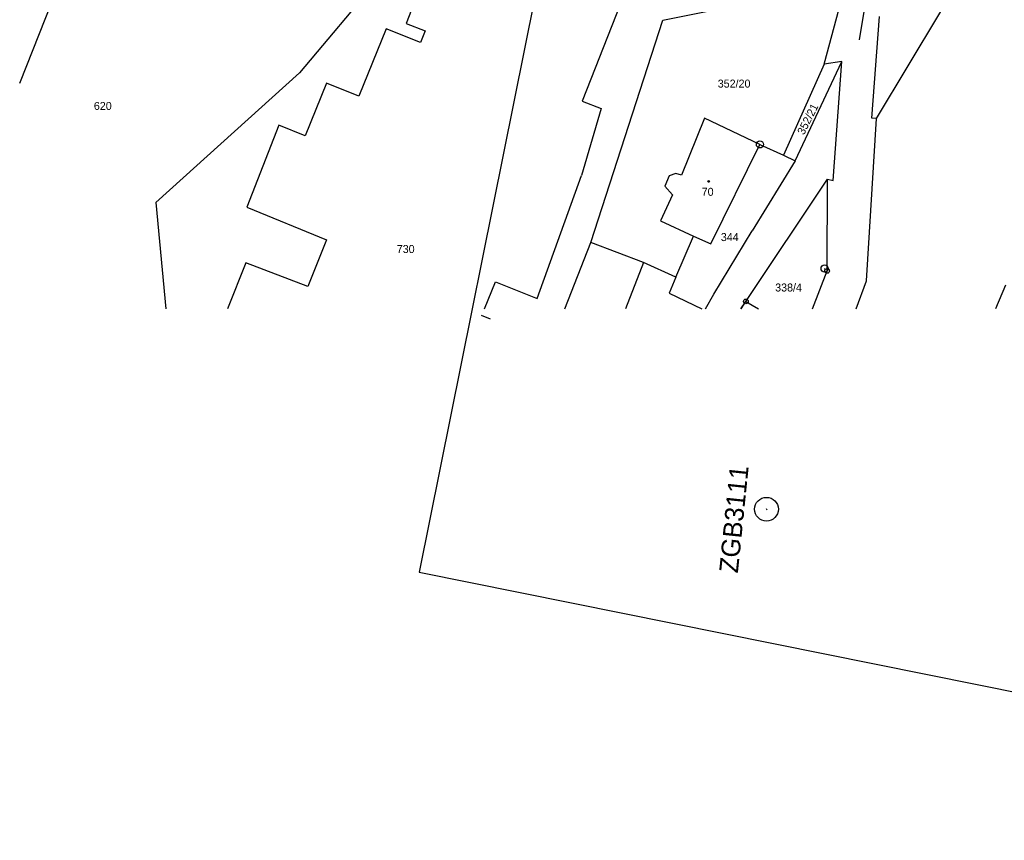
# Model space of a CAD drawing. Extents: x -778045 to -777594, y -1202682 to -1202213.
# Drawn here: x -778044.8 to -777835.6, y -1202682.1 to -1202507.7 of the extents above; entities that cross this region are included whole.
import ezdxf

# ---------------------------------------------------------------- set-up
doc = ezdxf.new("R2010")
doc.units = 0
for name, color, linetype in [('GD_Starý stav', 7, 'Continuous'), ('Katastr_HRANICE DRÁHY', 7, 'Continuous'), ('Katastr_Hranice parcel', 7, 'Continuous'), ('Katastr_Parcelní čísla', 7, 'Continuous'), ('Katastr_Slučkované čáry', 7, 'Continuous'), ('Katastr_Značky kultur', 7, 'Continuous'), ('ŽBP', 7, 'Continuous')]:
    doc.layers.add(name, color=color, linetype=linetype)

msp = doc.modelspace()

# ---------------------------------------------------------------- linework, layer by layer
at = {"layer": 'Defpoints'}
for p, q in [((-777877.12, -1202213.32), (-777959.92, -1202625.08)), ((-777959.92, -1202625.08), (-777676.59, -1202682.05))]:
    msp.add_line(p, q, dxfattribs=at)
at = {"layer": 'GD_Starý stav'}
msp.add_lwpolyline([(-777866.36, -1202511.98), (-777865.08, -1202504.23)], dxfattribs=at)
at = {"layer": 'Katastr_HRANICE DRÁHY'}
msp.add_line((-777876.32, -1202569.12), (-777873.23, -1202561.07), dxfattribs=at)
for points in [[(-777873.85, -1202517.11), (-777863.81, -1202479.74)], [(-777863.72, -1202528.63), (-777862.09, -1202506.98)], [(-777870.11, -1202516.58), (-777873.85, -1202517.11)], [(-777871.96, -1202541.84), (-777870.11, -1202516.58)], [(-777864.86, -1202563.15), (-777862.75, -1202528.64)], [(-777862.75, -1202528.64), (-777863.72, -1202528.63)], [(-777873.23, -1202561.07), (-777873.18, -1202541.55)], [(-777873.18, -1202541.55), (-777871.96, -1202541.84)], [(-777867.08, -1202569.12), (-777864.86, -1202563.15)]]:
    msp.add_lwpolyline(points, dxfattribs=at)
at = {"layer": 'Katastr_Hranice parcel'}
for p, q in [((-777890.49, -1202567.54), (-777873.18, -1202541.55)), ((-777891.54, -1202569.12), (-777890.49, -1202567.54)), ((-777891.5, -1202569.12), (-777890.49, -1202567.54)), ((-777890.49, -1202567.54), (-777887.81, -1202569.12))]:
    msp.add_line(p, q, dxfattribs=at)
for points in [[(-778044.79, -1202521.15), (-778028.2, -1202479.24)], [(-777862.75, -1202528.64), (-777835.8, -1202483.82)], [(-777910.86, -1202488.22), (-777925.26, -1202524.96)], [(-777958.02, -1202496.44), (-777962.7, -1202508.48)], [(-777968.38, -1202498.76), (-777985.35, -1202518.94)], [(-777908.12, -1202507.75), (-777897.16, -1202505.61)], [(-777962.7, -1202508.48), (-777958.65, -1202510.07)], [(-777923.42, -1202555.02), (-777908.12, -1202507.75)], [(-777966.94, -1202509.58), (-777972.76, -1202523.9)], [(-777959.61, -1202512.49), (-777966.94, -1202509.58)], [(-777958.65, -1202510.07), (-777959.61, -1202512.49)], [(-777873.85, -1202517.11), (-777882.51, -1202536.45)], [(-777879.99, -1202537.63), (-777870.11, -1202516.58)], [(-777985.35, -1202518.94), (-778015.88, -1202546.51)], [(-777979.63, -1202521.14), (-777984.15, -1202532.36)], [(-777972.76, -1202523.9), (-777979.63, -1202521.14)], [(-777925.26, -1202524.96), (-777921.27, -1202526.57)], [(-777921.27, -1202526.57), (-777925.41, -1202540.77)], [(-777899.26, -1202528.6), (-777904.18, -1202540.74)], [(-777887.51, -1202534.17), (-777899.26, -1202528.6)], [(-777989.7, -1202530.09), (-777996.5, -1202547.5)], [(-777984.15, -1202532.36), (-777989.7, -1202530.09)], [(-777897.93, -1202555.33), (-777887.51, -1202534.17)], [(-777887.51, -1202534.17), (-777882.51, -1202536.45)], [(-777879.99, -1202537.63), (-777889.12, -1202552.55)], [(-777882.51, -1202536.45), (-777879.99, -1202537.63)], [(-777934.83, -1202566.91), (-777925.41, -1202540.77)], [(-777906.81, -1202540.87), (-777907.73, -1202543.02)], [(-777905.37, -1202540.33), (-777906.81, -1202540.87)], [(-777904.18, -1202540.74), (-777905.37, -1202540.33)], [(-777907.73, -1202543.02), (-777906.08, -1202544.86)], [(-777906.08, -1202544.86), (-777908.65, -1202550.43)], [(-778015.88, -1202546.51), (-778013.77, -1202569.12)], [(-777996.5, -1202547.5), (-777979.62, -1202554.43)], [(-777908.65, -1202550.43), (-777901.6, -1202553.7)], [(-777897.33, -1202565.97), (-777889.12, -1202552.55)], [(-777979.62, -1202554.43), (-777983.6, -1202564.35)], [(-777905.35, -1202562.37), (-777901.6, -1202553.7)], [(-777901.6, -1202553.7), (-777897.93, -1202555.33)], [(-777928.99, -1202569.12), (-777923.42, -1202555.02)], [(-777912.25, -1202559.27), (-777923.42, -1202555.02)], [(-777996.72, -1202559.32), (-778000.62, -1202569.12)], [(-777983.6, -1202564.35), (-777996.72, -1202559.32)], [(-777905.35, -1202562.37), (-777912.25, -1202559.27)], [(-777905.35, -1202562.37), (-777906.79, -1202565.8)], [(-777946.06, -1202569.12), (-777943.69, -1202563.37)], [(-777943.69, -1202563.37), (-777934.83, -1202566.91)], [(-777835.36, -1202564.07), (-777837.48, -1202569.12)], [(-777906.79, -1202565.8), (-777899.83, -1202569.12)], [(-777899.1, -1202569.12), (-777897.33, -1202565.97)], [(-777944.76, -1202571.3), (-777946.65, -1202570.56)]]:
    msp.add_lwpolyline(points, dxfattribs=at)
at = {"layer": 'Katastr_Slučkované čáry'}
msp.add_lwpolyline([(-777912.25, -1202559.27), (-777916.1, -1202569.12)], dxfattribs=at)
at = {"layer": 'Katastr_Značky kultur'}
for p, q in [((-777887.56, -1202534.17), (-777887.46, -1202534.17)), ((-777873.82, -1202560.54), (-777873.72, -1202560.54)), ((-777873.28, -1202561.07), (-777873.18, -1202561.07)), ((-777890.54, -1202567.54), (-777890.44, -1202567.54))]:
    msp.add_line(p, q, dxfattribs=at)
for centre, radius in [((-777887.51, -1202534.17), 0.756), ((-777898.38, -1202542.05), 0.175), ((-777873.77, -1202560.54), 0.756), ((-777873.23, -1202561.07), 0.499), ((-777890.49, -1202567.54), 0.499)]:
    msp.add_circle(centre, radius, dxfattribs=at)
at = {"layer": 'ŽBP'}
msp.add_line((-777886.19, -1202611.55), (-777886.04, -1202611.85), dxfattribs=at)
msp.add_circle((-777886.11, -1202611.7), 2.52, dxfattribs=at)

# ---------------------------------------------------------------- texts
at = {"layer": 'Katastr_Parcelní čísla'}
for s, p in [('352/20', (-777896.47, -1202522.1)), ('620', (-778029.03, -1202526.85)), ('70', (-777899.88, -1202545.09)), ('344', (-777895.81, -1202554.71)), ('730', (-777964.67, -1202557.25)), ('338/4', (-777884.27, -1202565.43))]:
    msp.add_text(s, height=1.7, dxfattribs=at).set_placement(p)
msp.add_text('352/21', height=1.7, rotation=63.2589, dxfattribs=at).set_placement((-777878.15, -1202532.27))
at = {"layer": 'ŽBP'}
msp.add_text('ZGB3111', height=4, rotation=84.1988, dxfattribs=at).set_placement((-777892.2, -1202625.38))

doc.saveas('drawing.dxf')
